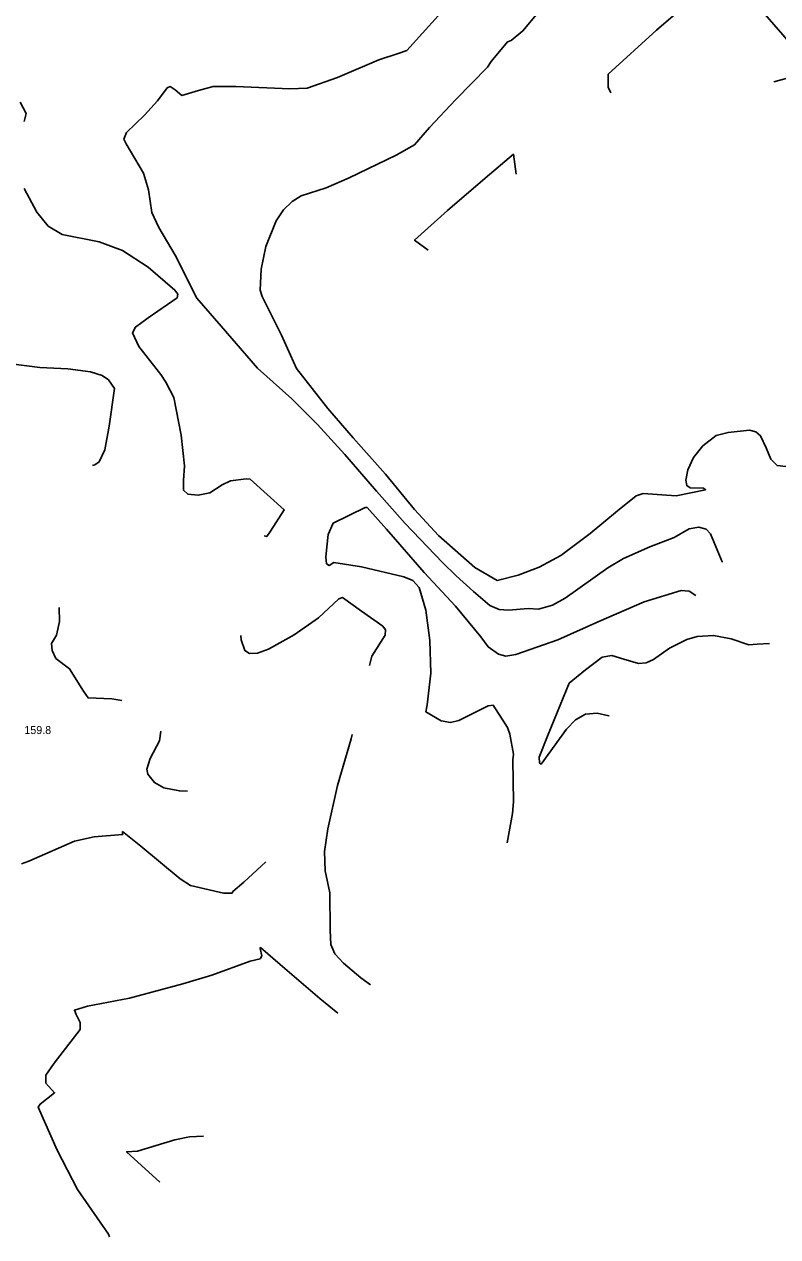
# Model space of a CAD drawing. Extents: x 1467615 to 2003689, y 770235 to 1108726.
# Drawn here: x 1999828.9 to 2000017.1, y 773781.3 to 774084.4 of the extents above; entities that cross this region are included whole.
import ezdxf

# ---------------------------------------------------------------- set-up
doc = ezdxf.new("R2010")
doc.units = 0
for name, color, linetype in [('RD_DTM_Major1', 7, 'Continuous'), ('RD_DTM_Minor1', 7, 'Continuous'), ('RD_DTM_Spot_Elev', 7, 'Continuous')]:
    doc.layers.add(name, color=color, linetype=linetype)

msp = doc.modelspace()

# ---------------------------------------------------------------- linework, layer by layer
at = {"layer": 'RD_DTM_Major1'}
for points in [[(2000016.08, 774069.99), (2000021.05, 774071.3), (2000024.18, 774073.33), (2000024.01, 774075.11), (2000018.33, 774081.77), (2000009.95, 774091.52), (2000007.61, 774094.24), (2000004.99, 774097.05), (2000004.26, 774097.34), (2000002.51, 774096.42), (1999995.61, 774090.57), (1999986.8, 774082.92), (1999974.75, 774071.88), (1999974.77, 774068.63), (1999975.4, 774067.24)], [(1999951.76, 774046.89), (1999951.07, 774051.9), (1999944.01, 774045.92), (1999934.61, 774037.87), (1999926.39, 774030.39), (1999929.73, 774027.91)]]:
    msp.add_lwpolyline(points, dxfattribs=at)
at = {"layer": 'RD_DTM_Minor1'}
for points in [[(1999958.93, 774089.31), (1999953.45, 774082.73), (1999950.48, 774080.36), (1999949.62, 774080.01), (1999945.54, 774075.05), (1999944.62, 774073.68), (1999936.66, 774065.58), (1999930.11, 774058.61), (1999926.33, 774054.22), (1999921.79, 774051.63), (1999910, 774045.97), (1999904.28, 774043.5), (1999898.05, 774041.47), (1999895.76, 774040.07), (1999893.61, 774038.04), (1999891.79, 774035.29), (1999889.22, 774028.8), (1999888.02, 774023.19), (1999887.83, 774017.89), (1999888.33, 774016.32), (1999893.08, 774006.68), (1999896.87, 773998.37), (1999904.69, 773988.38), (1999911.02, 773981.01), (1999919.08, 773971.89), (1999926.32, 773963.11), (1999932.33, 773956.6), (1999941.39, 773948.59), (1999947.01, 773945.36), (1999952.22, 773946.66), (1999957.47, 773948.65), (1999962.88, 773951.61), (1999970.27, 773957.06), (1999977.08, 773962.77), (1999981.76, 773966.54), (1999983.44, 773967.13), (1999988.15, 773966.75), (1999991.69, 773966.53), (1999999.07, 773968.02), (1999998.52, 773968.42), (1999995.22, 773968.49), (1999994.36, 773969.05), (1999994.13, 773970.46), (1999994.6, 773973.02), (1999996.01, 773976.12), (1999998.38, 773978.99), (2000001.71, 773981.57), (2000004.68, 773982.35), (2000010.06, 773982.95), (2000011.66, 773982.52), (2000012.82, 773981.51), (2000014.21, 773978.52), (2000015.35, 773975.7), (2000016.94, 773974.07), (2000019.15, 773973.81)], [(1999932.25, 774086.47), (1999924.41, 774077.85), (1999922.28, 774077.07), (1999917.45, 774075.48), (1999907.09, 774071.12), (1999899.55, 774068.42), (1999895.23, 774068.21), (1999881.67, 774068.85), (1999876.09, 774068.83), (1999872.39, 774067.84), (1999868.21, 774066.61), (1999866.57, 774068.02), (1999865.28, 774068.82), (1999864.56, 774068.48), (1999862.12, 774065.24), (1999858.87, 774061.66), (1999854.37, 774057.31), (1999853.74, 774055.68), (1999854.32, 774054.48), (1999858.64, 774047.19), (1999859.86, 774043.04), (1999860.7, 774037.3), (1999862.51, 774033.6), (1999866.58, 774026.64), (1999871.93, 774015.88), (1999878.07, 774008.91), (1999887.13, 773998.45), (1999895.7, 773990.78), (1999902.13, 773984.36), (1999908.91, 773976.81), (1999916.84, 773967.68), (1999924.04, 773959.61), (1999933.38, 773949.83), (1999936.75, 773946.53), (1999941.06, 773942.59), (1999945.15, 773939.1), (1999947.5, 773938.08), (1999949.84, 773937.96), (1999954.78, 773938.31), (1999957.36, 773938.14), (1999960.85, 773939.16), (1999963.95, 773940.93), (1999974.65, 773948.5), (1999978.57, 773950.81), (1999985.17, 773953.74), (1999991.23, 773956.07), (1999994.99, 773958.25), (1999997.42, 773958.68), (1999999.23, 773958.2), (2000000.27, 773956.99), (2000003.22, 773950.05), (2000003.24, 773949.94)], [(1999828.79, 774060.09), (1999829.29, 774062.11), (1999827.8, 774064.88)], [(1999888.77, 773956.54), (1999889.45, 773956.33), (1999890.36, 773957.71), (1999893.82, 773963.01), (1999885.32, 773970.67), (1999884.29, 773970.74), (1999880.42, 773970.23), (1999878.33, 773969.22), (1999875.25, 773967.26), (1999872.34, 773966.68), (1999869.76, 773966.93), (1999868.62, 773967.95), (1999868.64, 773970.31), (1999868.87, 773974.02), (1999868.03, 773981.71), (1999866.24, 773991.09), (1999864.26, 773994.95), (1999862.97, 773996.85), (1999857.44, 774003.84), (1999855.88, 774007.27), (1999856.68, 774008.69), (1999859.78, 774011.04), (1999867.07, 774016.02), (1999867.2, 774016.9), (1999866.5, 774017.94), (1999859.79, 774023.67), (1999853.42, 774027.87), (1999847.57, 774030.01), (1999838.34, 774031.84), (1999834.83, 774033.9), (1999832, 774037.43), (1999828.84, 774043.31)], [(1999845.92, 773974.08), (1999846.48, 773974.23), (1999847.54, 773975.03), (1999848.98, 773977.99), (1999850.06, 773983.89), (1999851.36, 773993.35), (1999849.93, 773995.47), (1999848.35, 773996.61), (1999845.39, 773997.52), (1999839.71, 773998.27), (1999832.74, 773998.56), (1999821.61, 773999.99)], [(1999949.46, 773879.79), (1999950.81, 773887.09), (1999951.07, 773890.05), (1999950.91, 773900.52), (1999951.07, 773901.94), (1999950.13, 773906.95), (1999949.61, 773908.56), (1999946, 773914.16), (1999944.76, 773914), (1999937.39, 773910.31), (1999935.35, 773909.89), (1999933.03, 773910.28), (1999929.22, 773912.51), (1999929.55, 773914.29), (1999930.44, 773922.18), (1999930.16, 773930.37), (1999929.14, 773937.91), (1999927.49, 773943.61), (1999925.91, 773945.31), (1999923.71, 773946.25), (1999913.08, 773948.74), (1999906.2, 773949.82), (1999905.05, 773949.1), (1999904.4, 773949.54), (1999904.18, 773951.17), (1999904.45, 773953.74), (1999904.77, 773956.82), (1999906.02, 773959.71), (1999914.02, 773963.56), (1999914.52, 773963.63), (1999919.32, 773958.15), (1999928.76, 773947.33), (1999936.59, 773938.9), (1999942.92, 773931.27), (1999944.75, 773928.78), (1999947.32, 773926.92), (1999949.14, 773926.47), (1999951.7, 773926.81), (1999962.12, 773930.53), (1999972.4, 773935.1), (1999983.73, 773940.04), (1999992.99, 773942.88), (1999994.97, 773942.64), (1999996.6, 773941.58)], [(1999915.12, 773924.13), (1999915.73, 773926.47), (1999919.05, 773931.67), (1999919.07, 773932.99), (1999918.44, 773933.9), (1999913.11, 773937.66), (1999908.34, 773941.09), (1999907.41, 773940.74), (1999902.38, 773936.01), (1999896.28, 773931.78), (1999889.87, 773928.18), (1999887.09, 773927.16), (1999885.14, 773927.11), (1999883.94, 773927.84), (1999883.02, 773930.51), (1999882.94, 773931.63)], [(1999853.24, 773915.33), (1999850.72, 773915.74), (1999844.79, 773916.01), (1999843.64, 773917.64), (1999840.16, 773923.3), (1999836.75, 773925.87), (1999835.81, 773927.88), (1999835.7, 773929.61), (1999836.92, 773931.65), (1999837.66, 773935.06), (1999837.6, 773938.59)], [(1999974.97, 773911.5), (1999974.94, 773911.51), (1999971.96, 773912.22), (1999969.08, 773911.97), (1999966.53, 773910.49), (1999964.35, 773908.15), (1999958, 773899.44), (1999957.59, 773899.75), (1999957.53, 773901.18), (1999959.71, 773906.89), (1999964.99, 773919.65), (1999969.07, 773923.05), (1999973.26, 773926.15), (1999975.67, 773926.6), (1999978.62, 773925.7), (1999982.27, 773924.63), (1999984.19, 773924.76), (1999986.08, 773925.61), (1999990.04, 773928.39), (1999994.38, 773930.62), (1999996.94, 773931.31), (2000001.07, 773931.6), (2000005.45, 773930.74), (2000009.88, 773929.29), (2000011.93, 773929.45), (2000015.05, 773929.61)], [(1999869.61, 773892.72), (1999867.61, 773892.75), (1999863.72, 773893.53), (1999861.38, 773894.84), (1999859.71, 773896.97), (1999859.45, 773898.22), (1999860.31, 773900.84), (1999862.67, 773905.3), (1999863, 773907.65)], [(1999915.36, 773844.26), (1999912.96, 773846.06), (1999908.6, 773849.66), (1999906.43, 773852.03), (1999905.48, 773854.38), (1999905.3, 773857.9), (1999905.2, 773867.28), (1999904.04, 773872.74), (1999903.87, 773877.63), (1999904.69, 773883.25), (1999907.13, 773894.13), (1999910.55, 773905.76), (1999910.81, 773906.84)], [(1999828.14, 773874.53), (1999830, 773875.21), (1999841.38, 773880.21), (1999846.28, 773881.23), (1999853.42, 773881.85), (1999853.4, 773882.58), (1999858.01, 773878.91), (1999867.82, 773870.73), (1999870.35, 773869.13), (1999878.64, 773867.18), (1999880.77, 773867.16), (1999880.98, 773867.59), (1999883.7, 773869.92), (1999889.23, 773875.03)], [(1999850.17, 773781.3), (1999849.86, 773781.92), (1999842.16, 773793.11), (1999837.05, 773802.97), (1999832.33, 773813.69), (1999832.81, 773814.47), (1999836.41, 773817.31), (1999834.28, 773819.73), (1999834.25, 773821.69), (1999836.29, 773824.67), (1999842.81, 773833.07), (1999842.78, 773834.89), (1999841.86, 773836.82), (1999841.38, 773837.93), (1999844.64, 773838.93), (1999855.13, 773840.97), (1999868.45, 773844.49), (1999875.73, 773846.68), (1999885.33, 773850.23), (1999887.78, 773850.78), (1999888.22, 773851.5), (1999887.79, 773853.36), (1999887.84, 773853.59), (1999892.8, 773849.39), (1999902.66, 773840.85), (1999907.2, 773837.23)], [(1999862.71, 773794.97), (1999854.4, 773802.53), (1999857.18, 773802.67), (1999866.46, 773805.57), (1999870.1, 773806.27), (1999873.62, 773806.44), (1999873.65, 773806.44)]]:
    msp.add_lwpolyline(points, dxfattribs=at)

# ---------------------------------------------------------------- texts
at = {"layer": 'RD_DTM_Spot_Elev'}
msp.add_text('159.8', height=2, dxfattribs=at).set_placement((1999828.88, 773906.97))

doc.saveas('drawing.dxf')
